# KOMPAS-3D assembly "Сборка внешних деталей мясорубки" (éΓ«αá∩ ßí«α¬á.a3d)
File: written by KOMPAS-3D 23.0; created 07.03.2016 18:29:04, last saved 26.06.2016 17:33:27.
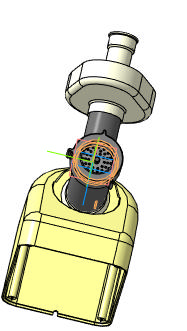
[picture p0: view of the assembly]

Document properties: Автор: Аня; Полное имя файла: C:\Users\zyrianova_ae\Desktop\Задание_колледж\Модели\Вторая сборка.a3d

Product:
- Component [detail]: Корпус  | Масса: 3.219485; Автор: Аня; source file: Корпус мясорубки.m3d
- Component [detail]: Прокладка(уплотнитель корпуса)  | Масса: 0.122335; Автор: Аня; source file: Прокладка(уплотнитель корпуса).m3d
- Component [detail]: Желоб  | Масса: 0.762477; Автор: Аня; source file: Желоб.m3d
- Component [detail]: Лоток  | Масса: 0.639455; Автор: Аня; source file: Лоток.m3d
- Component [detail]: Толкатель  | Масса: 0.279807; Автор: Аня; source file: Толкатель.m3d
- Component [detail]: Зажимное кольцо  | Масса: 0.331798; Автор: Аня; source file: Зажимное кольцо.m3d
- Component [detail]: Шнек  | Масса: 0.46846; Автор: Аня; source file: Шнек.m3d
- Component [detail]: Нож  | Масса: 0.008212; Автор: Аня; source file: Нож.m3d
- Component [detail]: Решетка  | Масса: 0.05681; Автор: Аня; source file: Решетка.m3d
- Part/product: Сборка внешних деталей мясорубки
    Масса: 5.888839

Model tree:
1. Сечение поверхностью:1
     Расстояние = 3; Расстояние = -80

Referenced files in C:\Users\zyrianova_ae\Desktop\Задание_колледж\Модели\: Корпус мясорубки.m3d, прокладка(уплотнитель корпуса).m3d, Желоб.m3d, Лоток.m3d, Толкатель.m3d, Зажимное кольцо.m3d, Шнек.m3d, Нож.m3d, Решетка.m3d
